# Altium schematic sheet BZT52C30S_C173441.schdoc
size 127 x 101 mm
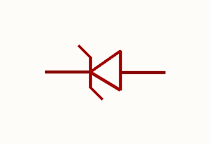
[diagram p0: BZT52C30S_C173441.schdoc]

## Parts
D?  bzt52c30s_c173441  [SOD-323_L1.8-W1.3-LS2.5-RD]  (value not drawn)

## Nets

Not connected (* = marked no-connect by the designer): D? 1 2

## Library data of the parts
D? = bzt52c30s_c173441: 二极管配置:1个独立式;稳压值(标称值):30V;稳压值(范围):28V~32V;耗散功率(Pd):200mW;; Manufacturer: MDD(辰达半导体); AddInBom: yes; ModelId: db63db13d9e342eb939127d413d6200b; ModelTransform: 104.3305,51.181,0,0,0,0,0,-0.004,0; Diode Configuration: 1个独立式; Zener Voltage(Nom): 30V; Reverse Leakage Current (Ir): 100nA@23V; Pd - Power Dissipation: 200mW; Impedance(Zzt): 80Ω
